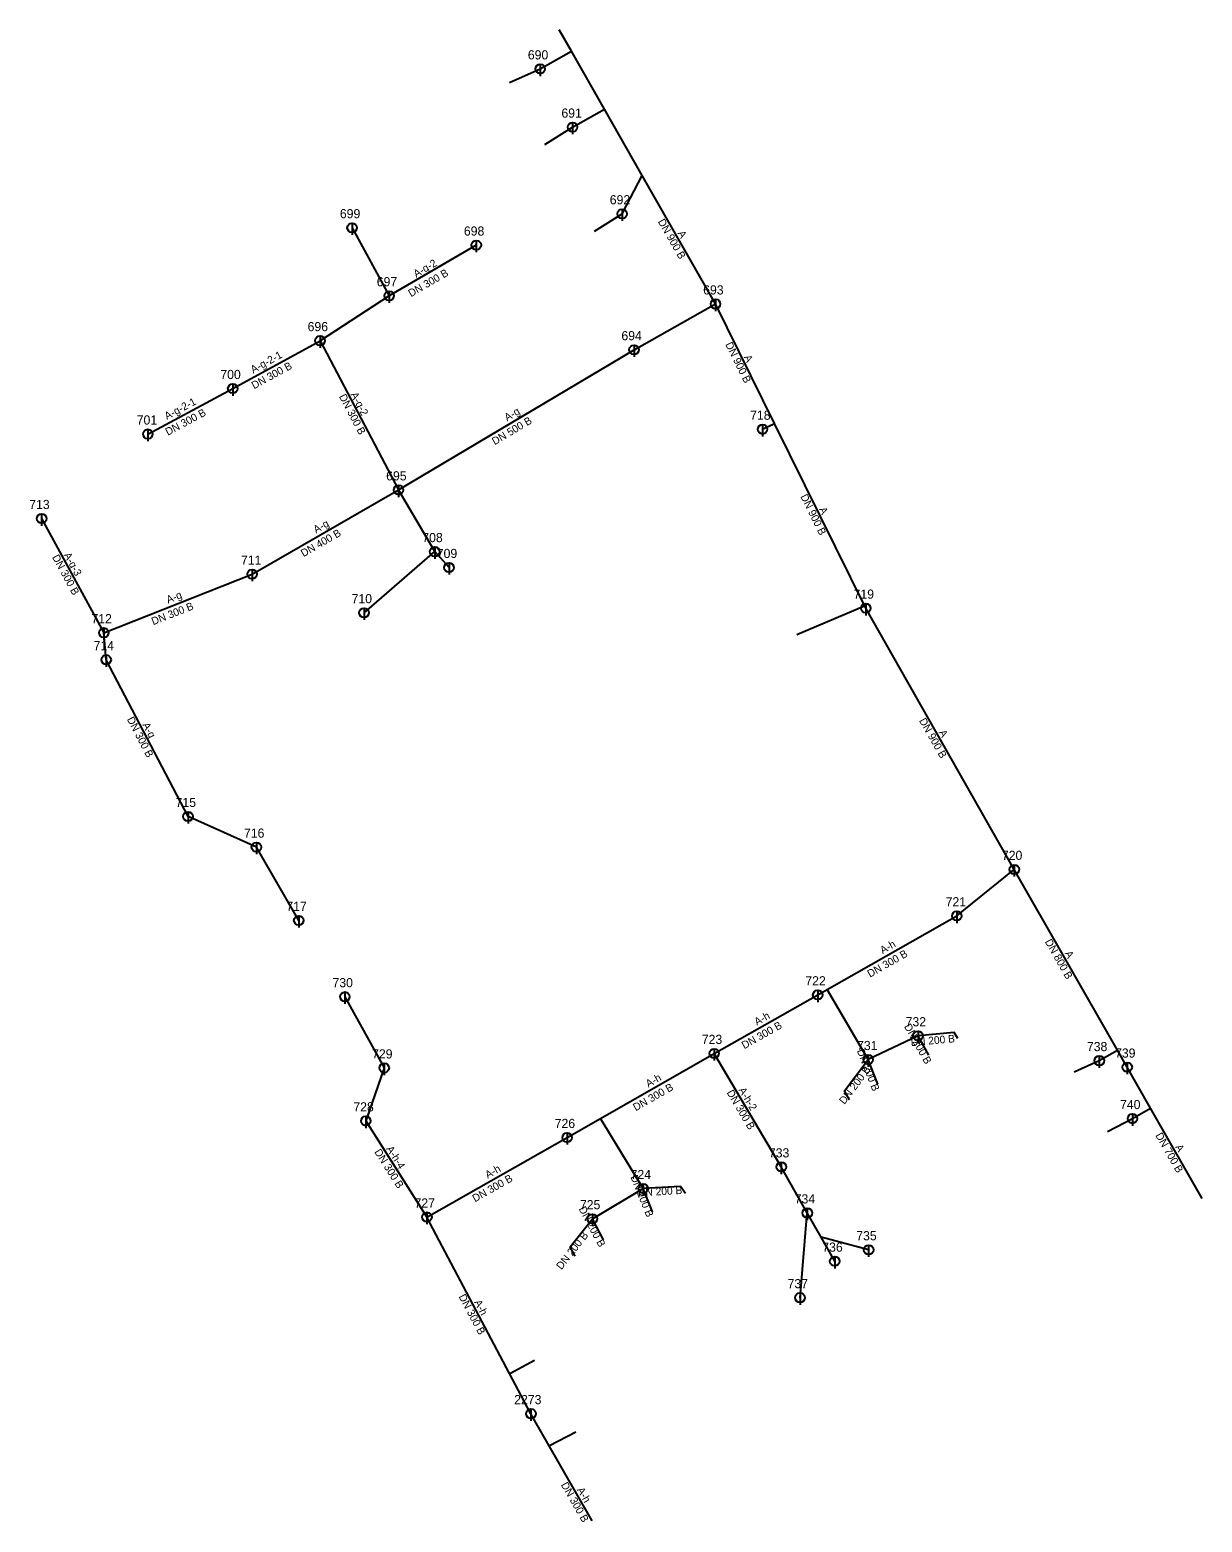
# Model space of a CAD drawing. Extents: x -443525 to -443278, y -1122830 to -1122516.
import ezdxf

# ---------------------------------------------------------------- set-up
doc = ezdxf.new("R2010")
doc.units = 0
for name, color, linetype in [('_pripojka_kanal_jednotna_priblizne_', 7, 'Continuous'), ('_stoka_jednotna_smvak_prevzato_z_dokumentace_', 7, 'Continuous'), ('Default', 7, 'Continuous'), ('MoLevel 119', 7, 'Continuous'), ('MoLevel 120', 7, 'Continuous'), ('MoLevel 124', 7, 'Continuous'), ('MoLevel 68', 7, 'Continuous'), ('MoLevel 69', 7, 'Continuous')]:
    doc.layers.add(name, color=color, linetype=linetype)

# ---------------------------------------------------------------- blocks, each defined once
blk = doc.blocks.new('_sachta_kanal_prevzato_z_dokumentace_')
at = {"layer": 'Default'}
blk.add_line((0, 0.00005), (0, -0.000075), dxfattribs=at)
blk.add_circle((0, 0), 0.00005, dxfattribs=at)

msp = doc.modelspace()

# ---------------------------------------------------------------- linework, layer by layer
at = {"layer": '_pripojka_kanal_jednotna_priblizne_'}
for p, q in [((-443423.95, -1122527.07), (-443417.49, -1122524.23)), ((-443416.52, -1122540.13), (-443410.7, -1122536.48)), ((-443406.05, -1122558.33), (-443400.26, -1122554.71)), ((-443363.49, -1122643.18), (-443349.25, -1122637.18)), ((-443335.75, -1122731.66), (-443338.02, -1122727.6)), ((-443346.51, -1122737.75), (-443348.51, -1122732.6)), ((-443305.18, -1122735.2), (-443299.89, -1122732.82)), ((-443298.17, -1122747.69), (-443292.92, -1122745.01)), ((-443393.85, -1122764.65), (-443395.82, -1122759.73)), ((-443404.17, -1122770.53), (-443406.53, -1122766.08)), ((-443418.67, -1122795.86), (-443423.88, -1122798.68)), ((-443410.03, -1122810.97), (-443415.56, -1122813.86))]:
    msp.add_line(p, q, dxfattribs=at)
for points in [[(-443329.64, -1122728.16), (-443330.45, -1122726.93), (-443338.02, -1122727.6)], [(-443352.41, -1122741.08), (-443353.5, -1122739.19), (-443348.51, -1122732.6)], [(-443386.97, -1122760.78), (-443388.02, -1122759.26), (-443395.82, -1122759.73)], [(-443410.13, -1122773.96), (-443411.17, -1122771.96), (-443406.53, -1122766.08)]]:
    msp.add_lwpolyline(points, dxfattribs=at)
at = {"layer": '_stoka_jednotna_smvak_prevzato_z_dokumentace_'}
for p, q in [((-443410.93, -1122520.51), (-443413.49, -1122516.01)), ((-443417.49, -1122524.23), (-443410.93, -1122520.51)), ((-443403.99, -1122532.67), (-443410.93, -1122520.51)), ((-443410.7, -1122536.48), (-443403.99, -1122532.67)), ((-443396.03, -1122546.63), (-443403.99, -1122532.67)), ((-443400.26, -1122554.71), (-443396.03, -1122546.63)), ((-443380.61, -1122573.67), (-443396.03, -1122546.63)), ((-443457.07, -1122557.64), (-443449.27, -1122571.95)), ((-443430.94, -1122561.29), (-443449.27, -1122571.95)), ((-443449.27, -1122571.95), (-443463.81, -1122581.39)), ((-443397.76, -1122583.3), (-443380.61, -1122573.67)), ((-443368.21, -1122598.78), (-443380.61, -1122573.67)), ((-443482.17, -1122591.46), (-443463.81, -1122581.39)), ((-443463.81, -1122581.39), (-443447.29, -1122612.78)), ((-443447.29, -1122612.78), (-443397.76, -1122583.3)), ((-443500.03, -1122601.03), (-443482.17, -1122591.46)), ((-443370.73, -1122600.02), (-443368.21, -1122598.78)), ((-443349.01, -1122637.66), (-443368.21, -1122598.78)), ((-443478.1, -1122630.5), (-443447.29, -1122612.78)), ((-443439.69, -1122625.76), (-443447.29, -1122612.78)), ((-443522.37, -1122618.8), (-443509.29, -1122642.82)), ((-443454.56, -1122638.62), (-443439.69, -1122625.76)), ((-443436.68, -1122629.1), (-443439.69, -1122625.76)), ((-443509.29, -1122642.82), (-443478.1, -1122630.5)), ((-443317.77, -1122692.6), (-443349.01, -1122637.66)), ((-443508.78, -1122648.49), (-443509.29, -1122642.82)), ((-443491.58, -1122681.47), (-443508.78, -1122648.49)), ((-443477.2, -1122687.92), (-443491.58, -1122681.47)), ((-443468.29, -1122703.33), (-443477.2, -1122687.92)), ((-443329.87, -1122702.37), (-443317.77, -1122692.6)), ((-443296.04, -1122730.63), (-443317.77, -1122692.6)), ((-443357.14, -1122717.86), (-443329.87, -1122702.37)), ((-443359.12, -1122718.99), (-443357.14, -1122717.86)), ((-443348.51, -1122732.6), (-443357.14, -1122717.86)), ((-443458.58, -1122719.38), (-443450.3, -1122734.36)), ((-443380.9, -1122731.31), (-443359.12, -1122718.99)), ((-443338.02, -1122727.6), (-443348.51, -1122732.6)), ((-443299.89, -1122732.82), (-443296.04, -1122730.63)), ((-443294.01, -1122734.19), (-443296.04, -1122730.63)), ((-443404.82, -1122745.01), (-443380.9, -1122731.31)), ((-443366.78, -1122755.18), (-443380.9, -1122731.31)), ((-443289.09, -1122742.83), (-443294.01, -1122734.19)), ((-443450.3, -1122734.36), (-443454.19, -1122745.5)), ((-443292.92, -1122745.01), (-443289.09, -1122742.83)), ((-443278.26, -1122761.84), (-443289.09, -1122742.83)), ((-443454.19, -1122745.5), (-443441.32, -1122765.72)), ((-443411.84, -1122748.99), (-443404.82, -1122745.01)), ((-443395.82, -1122759.74), (-443404.82, -1122745.01)), ((-443441.32, -1122765.72), (-443411.84, -1122748.99)), ((-443361.31, -1122764.86), (-443366.78, -1122755.18)), ((-443406.53, -1122766.08), (-443395.82, -1122759.74)), ((-443362.85, -1122782.68), (-443361.31, -1122764.86)), ((-443358.43, -1122769.94), (-443361.31, -1122764.86)), ((-443419.44, -1122807.08), (-443441.32, -1122765.72)), ((-443355.55, -1122775.01), (-443358.43, -1122769.94)), ((-443348.41, -1122772.61), (-443358.43, -1122769.94)), ((-443406.54, -1122829.62), (-443419.44, -1122807.08))]:
    msp.add_line(p, q, dxfattribs=at)

# ---------------------------------------------------------------- block references
at = {"layer": 'MoLevel 119', "xscale": 20000, "yscale": 20000}
for p in [(-443417.49, -1122524.23), (-443410.7, -1122536.48), (-443400.26, -1122554.71), (-443457.07, -1122557.64), (-443430.94, -1122561.29), (-443449.27, -1122571.95), (-443380.61, -1122573.67), (-443463.81, -1122581.39), (-443397.76, -1122583.3), (-443482.17, -1122591.46), (-443370.73, -1122600.02), (-443500.03, -1122601.03), (-443447.29, -1122612.78), (-443522.37, -1122618.8), (-443439.69, -1122625.76), (-443478.1, -1122630.5), (-443436.68, -1122629.1), (-443349.01, -1122637.66), (-443454.56, -1122638.62), (-443509.29, -1122642.82), (-443508.78, -1122648.49), (-443491.58, -1122681.47), (-443477.2, -1122687.92), (-443317.77, -1122692.6), (-443468.29, -1122703.33), (-443329.87, -1122702.37), (-443458.58, -1122719.38), (-443359.12, -1122718.99), (-443338.02, -1122727.6), (-443380.9, -1122731.31), (-443450.3, -1122734.36), (-443348.51, -1122732.6), (-443299.89, -1122732.82), (-443294.01, -1122734.19), (-443454.19, -1122745.5), (-443292.92, -1122745.01), (-443411.84, -1122748.99), (-443366.78, -1122755.18), (-443395.82, -1122759.73), (-443441.32, -1122765.72), (-443406.53, -1122766.08), (-443361.31, -1122764.86), (-443348.41, -1122772.61), (-443355.55, -1122775.01), (-443362.85, -1122782.68), (-443419.44, -1122807.08)]:
    msp.add_blockref('_sachta_kanal_prevzato_z_dokumentace_', p, dxfattribs=at)

# ---------------------------------------------------------------- texts
at = {"layer": 'MoLevel 120'}
for s, p in [('690', (-443420.1, -1122522.23)), ('691', (-443413.04, -1122534.48)), ('692', (-443402.87, -1122552.71)), ('699', (-443459.64, -1122555.64)), ('698', (-443433.55, -1122559.29)), ('697', (-443451.88, -1122569.95)), ('693', (-443383.22, -1122571.67)), ('696', (-443466.42, -1122579.39)), ('694', (-443400.42, -1122581.3)), ('700', (-443484.78, -1122589.46)), ('718', (-443373.34, -1122598.02)), ('701', (-443502.37, -1122599.03)), ('695', (-443449.9, -1122610.78)), ('713', (-443524.98, -1122616.8)), ('708', (-443442.3, -1122623.76)), ('711', (-443480.44, -1122628.5)), ('709', (-443439.25, -1122627.1)), ('719', (-443351.58, -1122635.66)), ('710', (-443457.17, -1122636.62)), ('712', (-443511.9, -1122640.82)), ('714', (-443511.44, -1122646.49)), ('715', (-443494.19, -1122679.47)), ('716', (-443479.81, -1122685.92)), ('720', (-443320.38, -1122690.6)), ('717', (-443470.9, -1122701.33)), ('721', (-443332.21, -1122700.37)), ('722', (-443361.73, -1122716.99)), ('730', (-443461.19, -1122717.38)), ('732', (-443340.63, -1122725.6)), ('723', (-443383.51, -1122729.31)), ('729', (-443452.86, -1122732.36)), ('731', (-443350.85, -1122730.6)), ('738', (-443302.5, -1122730.82)), ('739', (-443296.58, -1122732.19)), ('728', (-443456.8, -1122743.5)), ('740', (-443295.53, -1122743.01)), ('726', (-443414.45, -1122746.99)), ('733', (-443369.39, -1122753.18)), ('724', (-443398.48, -1122757.73)), ('727', (-443443.93, -1122763.72)), ('725', (-443409.14, -1122764.08)), ('734', (-443363.97, -1122762.86)), ('735', (-443351.02, -1122770.61)), ('736', (-443358.16, -1122773.01)), ('737', (-443365.46, -1122780.68)), ('2273', (-443422.97, -1122805.08))]:
    msp.add_text(s, height=1.926, dxfattribs=at).set_placement(p)
at = {"layer": 'MoLevel 124'}
for rotation, p in [(299.2736, (-443341.02, -1122725.62)), (5.082, (-443339.48, -1122729.77)), (291.247, (-443350.91, -1122730.73)), (52.8824, (-443353.5, -1122742.14)), (291.9381, (-443398.55, -1122757.27)), (3.4765, (-443396.86, -1122761.41)), (297.9618, (-443409.45, -1122763.99)), (51.727, (-443413.03, -1122776.91))]:
    msp.add_text('DN 200 B', height=1.605, rotation=rotation, dxfattribs=at).set_placement(p)
at = {"layer": 'MoLevel 68'}
for s, rotation, p in [('DN 900 B', 299.6942, (-443392.8, -1122556.33)), ('DN 300 B', 30.1833, (-443444.68, -1122572.26)), ('DN 900 B', 296.2814, (-443378.61, -1122582.15)), ('DN 300 B', 28.7437, (-443477.68, -1122591.63)), ('DN 300 B', 297.757, (-443459.87, -1122593.12)), ('DN 300 B', 28.1839, (-443495.83, -1122601.4)), ('DN 500 B', 30.7609, (-443427.06, -1122603.4)), ('DN 900 B', 296.2814, (-443362.81, -1122614.14)), ('DN 400 B', 29.9048, (-443467.29, -1122626.94)), ('DN 300 B', 298.5703, (-443520.22, -1122626.91)), ('DN 300 B', 21.5539, (-443498.9, -1122641.24)), ('DN 300 B', 297.5405, (-443504.48, -1122661)), ('DN 900 B', 299.6234, (-443337.86, -1122661.31)), ('DN 800 B', 299.7394, (-443311.39, -1122707.8)), ('DN 300 B', 29.606, (-443348.13, -1122715.39)), ('DN 300 B', 29.495, (-443374.57, -1122730.44)), ('DN 300 B', 29.799, (-443397.4, -1122743.48)), ('DN 300 B', 300.6059, (-443378.33, -1122739.53)), ('DN 700 B', 299.6686, (-443288.15, -1122748.52)), ('DN 300 B', 302.4767, (-443452.45, -1122752.02)), ('DN 300 B', 29.5751, (-443431.21, -1122762.63)), ('DN 300 B', 297.8794, (-443434.71, -1122782.44)), ('DN 300 B', 299.7909, (-443413.19, -1122822.03))]:
    msp.add_text(s, height=1.605, rotation=rotation, dxfattribs=at).set_placement(p)
at = {"layer": 'MoLevel 69'}
for s, height, rotation, p in [('A', 1.6, 299.6942, (-443388.64, -1122558.78)), ('A-g-2', 1.605, 30.1833, (-443443.6, -1122568.17)), ('A-g-2-1', 1.605, 28.7437, (-443477.88, -1122588.31)), ('A', 1.6, 296.2814, (-443374.7, -1122584.84)), ('A-g-2', 1.605, 297.757, (-443457.44, -1122592.7)), ('A-g-2-1', 1.605, 28.1839, (-443496.02, -1122598.08)), ('A-g', 1.605, 30.7609, (-443424.46, -1122598.39)), ('A', 1.6, 296.2814, (-443358.9, -1122616.84)), ('A-g', 1.605, 29.9048, (-443464.65, -1122621.96)), ('A-g-3', 1.605, 298.5703, (-443517.77, -1122626.45)), ('A-g', 1.605, 21.5539, (-443495.79, -1122636.69)), ('A-g', 1.605, 297.5405, (-443501.22, -1122662.18)), ('A', 1.6, 299.6234, (-443333.71, -1122663.77)), ('A-h', 1.605, 29.606, (-443345.46, -1122710.43)), ('A', 1.6, 299.7394, (-443307.23, -1122710.25)), ('A-h', 1.605, 29.495, (-443371.91, -1122725.49)), ('A-h', 1.605, 29.799, (-443394.75, -1122738.51)), ('A-h-2', 1.605, 300.6059, (-443375.84, -1122738.99)), ('A-h-4', 1.605, 302.4767, (-443449.95, -1122751.36)), ('A', 1.6, 299.6686, (-443284, -1122750.97)), ('A-h', 1.605, 29.5751, (-443428.54, -1122757.67)), ('A-h', 1.605, 297.8794, (-443431.43, -1122783.61)), ('A-h', 1.605, 299.7909, (-443409.82, -1122823.08))]:
    msp.add_text(s, height=height, rotation=rotation, dxfattribs=at).set_placement(p)

doc.saveas('drawing.dxf')
